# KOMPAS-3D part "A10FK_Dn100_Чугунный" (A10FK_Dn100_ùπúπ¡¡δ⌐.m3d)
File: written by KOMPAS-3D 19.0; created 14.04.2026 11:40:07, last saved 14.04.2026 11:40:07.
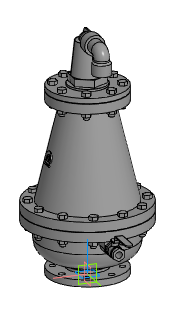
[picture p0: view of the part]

Document properties: Автор: Энергия; Полное имя файла: Z:\3.Личные\kachalov\3d для проектировщиков\x.x Тип A10FK Двухступенчатый воздухоотводчик\stp_Тип A10FK Двухступенчатый воздухоотводчик\A10FK_Dn100_Чугунный.m3d

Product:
- Part/product: A10FK_Dn100_Чугунный

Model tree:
1. Операция без истории:1  (labels: A10FK_Dn100_Чугунный)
